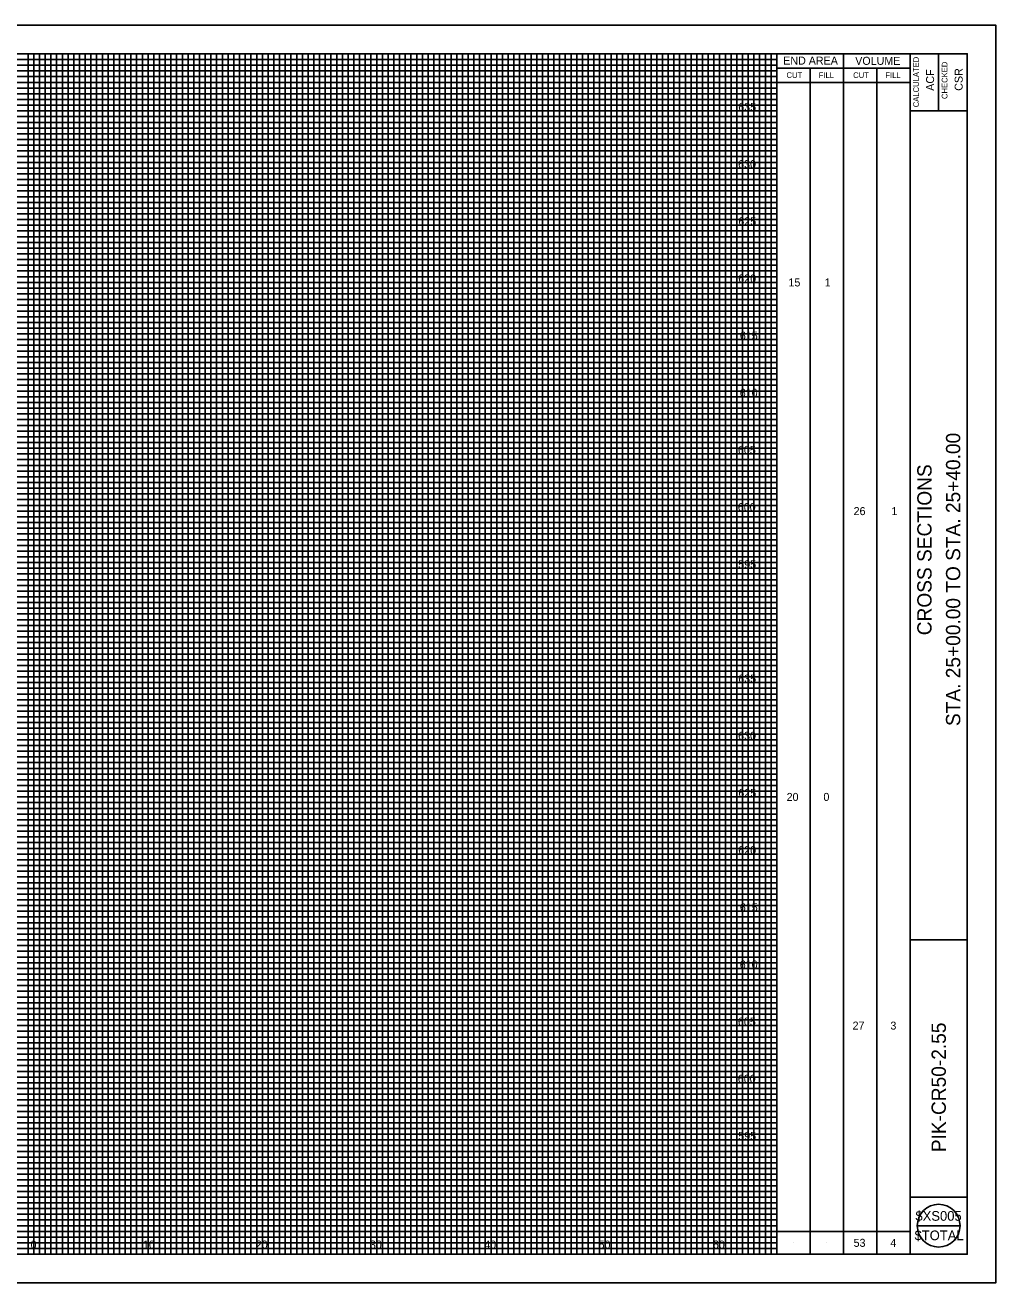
# Model space of a CAD drawing. Extents: x 1858928 to 1859278, y 421672 to 422012.
# Drawn here: x 1859192.6 to 1859277.5, y 421786.6 to 421896.6 of the extents above; entities that cross this region are included whole.
import ezdxf

# ---------------------------------------------------------------- set-up
doc = ezdxf.new("R2010")
doc.units = 0
for name, color, linetype in [('SH_Border', 7, 'Continuous'), ('SH_Cut_Line', 7, 'Continuous'), ('SH_Data', 7, 'Continuous'), ('SH_Major_Grid_Line', 7, 'Continuous'), ('SH_Minor_Grid_Line', 7, 'Continuous'), ('SH_Text', 7, 'Continuous')]:
    doc.layers.add(name, color=color, linetype=linetype)

msp = doc.modelspace()

# ---------------------------------------------------------------- linework, layer by layer
at = {"layer": 'SH_Border'}
for p, q in [((1859270.03, 421789.11), (1859270.03, 421894.11)), ((1859272.53, 421894.11), (1859272.53, 421889.11)), ((1859270.03, 421889.11), (1859275.03, 421889.11)), ((1859270.03, 421816.61), (1859275.03, 421816.61)), ((1859270.03, 421794.11), (1859275.03, 421794.11))]:
    msp.add_line(p, q, dxfattribs=at)
msp.add_lwpolyline([(1859117.53, 421894.11), (1859275.03, 421894.11), (1859275.03, 421789.11), (1859117.53, 421789.11)], close=True, dxfattribs=at)
at = {"layer": 'SH_Cut_Line'}
msp.add_lwpolyline([(1859107.53, 421786.61), (1859277.53, 421786.61), (1859277.53, 421896.61), (1859107.53, 421896.61)], close=True, dxfattribs=at)
at = {"layer": 'SH_Data'}
for p, q in [((1859258.37, 421789.11), (1859258.37, 421894.11)), ((1859264.2, 421789.11), (1859264.2, 421894.11)), ((1859258.37, 421892.86), (1859270.03, 421892.86)), ((1859261.28, 421789.11), (1859261.28, 421892.86)), ((1859267.12, 421789.11), (1859267.12, 421892.86)), ((1859258.37, 421891.61), (1859270.03, 421891.61)), ((1859258.37, 421791.11), (1859270.03, 421791.11)), ((1859270.66, 421791.61), (1859274.41, 421791.61)), ((1859259.83, 421790.11), (1859259.83, 421790.11)), ((1859262.74, 421790.11), (1859262.74, 421790.11)), ((1859265.66, 421790.11), (1859265.66, 421790.11)), ((1859268.58, 421790.11), (1859268.58, 421790.11))]:
    msp.add_line(p, q, dxfattribs=at)
msp.add_circle((1859272.53, 421791.61), 1.87, dxfattribs=at)
at = {"layer": 'SH_Major_Grid_Line'}
for p, q in [((1859193.37, 421789.11), (1859193.37, 421894.11)), ((1859198.37, 421789.11), (1859198.37, 421894.11)), ((1859203.37, 421789.11), (1859203.37, 421894.11)), ((1859208.37, 421789.11), (1859208.37, 421894.11)), ((1859213.37, 421789.11), (1859213.37, 421894.11)), ((1859218.37, 421789.11), (1859218.37, 421894.11)), ((1859223.37, 421789.11), (1859223.37, 421894.11)), ((1859228.37, 421789.11), (1859228.37, 421894.11)), ((1859233.37, 421789.11), (1859233.37, 421894.11)), ((1859238.37, 421789.11), (1859238.37, 421894.11)), ((1859243.37, 421789.11), (1859243.37, 421894.11)), ((1859248.37, 421789.11), (1859248.37, 421894.11)), ((1859253.37, 421789.11), (1859253.37, 421894.11)), ((1859123.37, 421889.11), (1859258.37, 421889.11)), ((1859123.37, 421884.11), (1859258.37, 421884.11)), ((1859123.37, 421879.11), (1859258.37, 421879.11)), ((1859123.37, 421874.11), (1859258.37, 421874.11)), ((1859123.37, 421869.11), (1859258.37, 421869.11)), ((1859123.37, 421864.11), (1859258.37, 421864.11)), ((1859123.37, 421859.11), (1859258.37, 421859.11)), ((1859123.37, 421854.11), (1859258.37, 421854.11)), ((1859123.37, 421849.11), (1859258.37, 421849.11)), ((1859123.37, 421844.11), (1859258.37, 421844.11)), ((1859123.37, 421839.11), (1859258.37, 421839.11)), ((1859123.37, 421834.11), (1859258.37, 421834.11)), ((1859123.37, 421829.11), (1859258.37, 421829.11)), ((1859123.37, 421824.11), (1859258.37, 421824.11)), ((1859123.37, 421819.11), (1859258.37, 421819.11)), ((1859123.37, 421814.11), (1859258.37, 421814.11)), ((1859123.37, 421809.11), (1859258.37, 421809.11)), ((1859123.37, 421804.11), (1859258.37, 421804.11)), ((1859123.37, 421799.11), (1859258.37, 421799.11)), ((1859123.37, 421794.11), (1859258.37, 421794.11))]:
    msp.add_line(p, q, dxfattribs=at)
at = {"layer": 'SH_Minor_Grid_Line'}
for p, q in [((1859192.87, 421789.11), (1859192.87, 421894.11)), ((1859193.87, 421789.11), (1859193.87, 421894.11)), ((1859194.37, 421789.11), (1859194.37, 421894.11)), ((1859194.87, 421789.11), (1859194.87, 421894.11)), ((1859195.37, 421789.11), (1859195.37, 421894.11)), ((1859195.87, 421789.11), (1859195.87, 421894.11)), ((1859196.37, 421789.11), (1859196.37, 421894.11)), ((1859196.87, 421789.11), (1859196.87, 421894.11)), ((1859197.37, 421789.11), (1859197.37, 421894.11)), ((1859197.87, 421789.11), (1859197.87, 421894.11)), ((1859198.87, 421789.11), (1859198.87, 421894.11)), ((1859199.37, 421789.11), (1859199.37, 421894.11)), ((1859199.87, 421789.11), (1859199.87, 421894.11)), ((1859200.37, 421789.11), (1859200.37, 421894.11)), ((1859200.87, 421789.11), (1859200.87, 421894.11)), ((1859201.37, 421789.11), (1859201.37, 421894.11)), ((1859201.87, 421789.11), (1859201.87, 421894.11)), ((1859202.37, 421789.11), (1859202.37, 421894.11)), ((1859202.87, 421789.11), (1859202.87, 421894.11)), ((1859203.87, 421789.11), (1859203.87, 421894.11)), ((1859204.37, 421789.11), (1859204.37, 421894.11)), ((1859204.87, 421789.11), (1859204.87, 421894.11)), ((1859205.37, 421789.11), (1859205.37, 421894.11)), ((1859205.87, 421789.11), (1859205.87, 421894.11)), ((1859206.37, 421789.11), (1859206.37, 421894.11)), ((1859206.87, 421789.11), (1859206.87, 421894.11)), ((1859207.37, 421789.11), (1859207.37, 421894.11)), ((1859207.87, 421789.11), (1859207.87, 421894.11)), ((1859208.87, 421789.11), (1859208.87, 421894.11)), ((1859209.37, 421789.11), (1859209.37, 421894.11)), ((1859209.87, 421789.11), (1859209.87, 421894.11)), ((1859210.37, 421789.11), (1859210.37, 421894.11)), ((1859210.87, 421789.11), (1859210.87, 421894.11)), ((1859211.37, 421789.11), (1859211.37, 421894.11)), ((1859211.87, 421789.11), (1859211.87, 421894.11)), ((1859212.37, 421789.11), (1859212.37, 421894.11)), ((1859212.87, 421789.11), (1859212.87, 421894.11)), ((1859213.87, 421789.11), (1859213.87, 421894.11)), ((1859214.37, 421789.11), (1859214.37, 421894.11)), ((1859214.87, 421789.11), (1859214.87, 421894.11)), ((1859215.37, 421789.11), (1859215.37, 421894.11)), ((1859215.87, 421789.11), (1859215.87, 421894.11)), ((1859216.37, 421789.11), (1859216.37, 421894.11)), ((1859216.87, 421789.11), (1859216.87, 421894.11)), ((1859217.37, 421789.11), (1859217.37, 421894.11)), ((1859217.87, 421789.11), (1859217.87, 421894.11)), ((1859218.87, 421789.11), (1859218.87, 421894.11)), ((1859219.37, 421789.11), (1859219.37, 421894.11)), ((1859219.87, 421789.11), (1859219.87, 421894.11)), ((1859220.37, 421789.11), (1859220.37, 421894.11)), ((1859220.87, 421789.11), (1859220.87, 421894.11)), ((1859221.37, 421789.11), (1859221.37, 421894.11)), ((1859221.87, 421789.11), (1859221.87, 421894.11)), ((1859222.37, 421789.11), (1859222.37, 421894.11)), ((1859222.87, 421789.11), (1859222.87, 421894.11)), ((1859223.87, 421789.11), (1859223.87, 421894.11)), ((1859224.37, 421789.11), (1859224.37, 421894.11)), ((1859224.87, 421789.11), (1859224.87, 421894.11)), ((1859225.37, 421789.11), (1859225.37, 421894.11)), ((1859225.87, 421789.11), (1859225.87, 421894.11)), ((1859226.37, 421789.11), (1859226.37, 421894.11)), ((1859226.87, 421789.11), (1859226.87, 421894.11)), ((1859227.37, 421789.11), (1859227.37, 421894.11)), ((1859227.87, 421789.11), (1859227.87, 421894.11)), ((1859228.87, 421789.11), (1859228.87, 421894.11)), ((1859229.37, 421789.11), (1859229.37, 421894.11)), ((1859229.87, 421789.11), (1859229.87, 421894.11)), ((1859230.37, 421789.11), (1859230.37, 421894.11)), ((1859230.87, 421789.11), (1859230.87, 421894.11)), ((1859231.37, 421789.11), (1859231.37, 421894.11)), ((1859231.87, 421789.11), (1859231.87, 421894.11)), ((1859232.37, 421789.11), (1859232.37, 421894.11)), ((1859232.87, 421789.11), (1859232.87, 421894.11)), ((1859233.87, 421789.11), (1859233.87, 421894.11)), ((1859234.37, 421789.11), (1859234.37, 421894.11)), ((1859234.87, 421789.11), (1859234.87, 421894.11)), ((1859235.37, 421789.11), (1859235.37, 421894.11)), ((1859235.87, 421789.11), (1859235.87, 421894.11)), ((1859236.37, 421789.11), (1859236.37, 421894.11)), ((1859236.87, 421789.11), (1859236.87, 421894.11)), ((1859237.37, 421789.11), (1859237.37, 421894.11)), ((1859237.87, 421789.11), (1859237.87, 421894.11)), ((1859238.87, 421789.11), (1859238.87, 421894.11)), ((1859239.37, 421789.11), (1859239.37, 421894.11)), ((1859239.87, 421789.11), (1859239.87, 421894.11)), ((1859240.37, 421789.11), (1859240.37, 421894.11)), ((1859240.87, 421789.11), (1859240.87, 421894.11)), ((1859241.37, 421789.11), (1859241.37, 421894.11)), ((1859241.87, 421789.11), (1859241.87, 421894.11)), ((1859242.37, 421789.11), (1859242.37, 421894.11)), ((1859242.87, 421789.11), (1859242.87, 421894.11)), ((1859243.87, 421789.11), (1859243.87, 421894.11)), ((1859244.37, 421789.11), (1859244.37, 421894.11)), ((1859244.87, 421789.11), (1859244.87, 421894.11)), ((1859245.37, 421789.11), (1859245.37, 421894.11)), ((1859245.87, 421789.11), (1859245.87, 421894.11)), ((1859246.37, 421789.11), (1859246.37, 421894.11)), ((1859246.87, 421789.11), (1859246.87, 421894.11)), ((1859247.37, 421789.11), (1859247.37, 421894.11)), ((1859247.87, 421789.11), (1859247.87, 421894.11)), ((1859248.87, 421789.11), (1859248.87, 421894.11)), ((1859249.37, 421789.11), (1859249.37, 421894.11)), ((1859249.87, 421789.11), (1859249.87, 421894.11)), ((1859250.37, 421789.11), (1859250.37, 421894.11)), ((1859250.87, 421789.11), (1859250.87, 421894.11)), ((1859251.37, 421789.11), (1859251.37, 421894.11)), ((1859251.87, 421789.11), (1859251.87, 421894.11)), ((1859252.37, 421789.11), (1859252.37, 421894.11)), ((1859252.87, 421789.11), (1859252.87, 421894.11)), ((1859253.87, 421789.11), (1859253.87, 421894.11)), ((1859254.37, 421789.11), (1859254.37, 421894.11)), ((1859254.87, 421789.11), (1859254.87, 421894.11)), ((1859255.37, 421789.11), (1859255.37, 421894.11)), ((1859255.87, 421789.11), (1859255.87, 421894.11)), ((1859256.37, 421789.11), (1859256.37, 421894.11)), ((1859256.87, 421789.11), (1859256.87, 421894.11)), ((1859257.37, 421789.11), (1859257.37, 421894.11)), ((1859257.87, 421789.11), (1859257.87, 421894.11)), ((1859123.37, 421893.61), (1859258.37, 421893.61)), ((1859123.37, 421893.11), (1859258.37, 421893.11)), ((1859123.37, 421892.61), (1859258.37, 421892.61)), ((1859123.37, 421892.11), (1859258.37, 421892.11)), ((1859123.37, 421891.61), (1859258.37, 421891.61)), ((1859123.37, 421891.11), (1859258.37, 421891.11)), ((1859123.37, 421890.61), (1859258.37, 421890.61)), ((1859123.37, 421890.11), (1859258.37, 421890.11)), ((1859123.37, 421889.61), (1859258.37, 421889.61)), ((1859123.37, 421888.61), (1859258.37, 421888.61)), ((1859123.37, 421888.11), (1859258.37, 421888.11)), ((1859123.37, 421887.61), (1859258.37, 421887.61)), ((1859123.37, 421887.11), (1859258.37, 421887.11)), ((1859123.37, 421886.61), (1859258.37, 421886.61)), ((1859123.37, 421886.11), (1859258.37, 421886.11)), ((1859123.37, 421885.61), (1859258.37, 421885.61)), ((1859123.37, 421885.11), (1859258.37, 421885.11)), ((1859123.37, 421884.61), (1859258.37, 421884.61)), ((1859123.37, 421883.61), (1859258.37, 421883.61)), ((1859123.37, 421883.11), (1859258.37, 421883.11)), ((1859123.37, 421882.61), (1859258.37, 421882.61)), ((1859123.37, 421882.11), (1859258.37, 421882.11)), ((1859123.37, 421881.61), (1859258.37, 421881.61)), ((1859123.37, 421881.11), (1859258.37, 421881.11)), ((1859123.37, 421880.61), (1859258.37, 421880.61)), ((1859123.37, 421880.11), (1859258.37, 421880.11)), ((1859123.37, 421879.61), (1859258.37, 421879.61)), ((1859123.37, 421878.61), (1859258.37, 421878.61)), ((1859123.37, 421878.11), (1859258.37, 421878.11)), ((1859123.37, 421877.61), (1859258.37, 421877.61)), ((1859123.37, 421877.11), (1859258.37, 421877.11)), ((1859123.37, 421876.61), (1859258.37, 421876.61)), ((1859123.37, 421876.11), (1859258.37, 421876.11)), ((1859123.37, 421875.61), (1859258.37, 421875.61)), ((1859123.37, 421875.11), (1859258.37, 421875.11)), ((1859123.37, 421874.61), (1859258.37, 421874.61)), ((1859123.37, 421873.61), (1859258.37, 421873.61)), ((1859123.37, 421873.11), (1859258.37, 421873.11)), ((1859123.37, 421872.61), (1859258.37, 421872.61)), ((1859123.37, 421872.11), (1859258.37, 421872.11)), ((1859123.37, 421871.61), (1859258.37, 421871.61)), ((1859123.37, 421871.11), (1859258.37, 421871.11)), ((1859123.37, 421870.61), (1859258.37, 421870.61)), ((1859123.37, 421870.11), (1859258.37, 421870.11)), ((1859123.37, 421869.61), (1859258.37, 421869.61)), ((1859123.37, 421868.61), (1859258.37, 421868.61)), ((1859123.37, 421868.11), (1859258.37, 421868.11)), ((1859123.37, 421867.61), (1859258.37, 421867.61)), ((1859123.37, 421867.11), (1859258.37, 421867.11)), ((1859123.37, 421866.61), (1859258.37, 421866.61)), ((1859123.37, 421866.11), (1859258.37, 421866.11)), ((1859123.37, 421865.61), (1859258.37, 421865.61)), ((1859123.37, 421865.11), (1859258.37, 421865.11)), ((1859123.37, 421864.61), (1859258.37, 421864.61)), ((1859123.37, 421863.61), (1859258.37, 421863.61)), ((1859123.37, 421863.11), (1859258.37, 421863.11)), ((1859123.37, 421862.61), (1859258.37, 421862.61)), ((1859123.37, 421862.11), (1859258.37, 421862.11)), ((1859123.37, 421861.61), (1859258.37, 421861.61)), ((1859123.37, 421861.11), (1859258.37, 421861.11)), ((1859123.37, 421860.61), (1859258.37, 421860.61)), ((1859123.37, 421860.11), (1859258.37, 421860.11)), ((1859123.37, 421859.61), (1859258.37, 421859.61)), ((1859123.37, 421858.61), (1859258.37, 421858.61)), ((1859123.37, 421858.11), (1859258.37, 421858.11)), ((1859123.37, 421857.61), (1859258.37, 421857.61)), ((1859123.37, 421857.11), (1859258.37, 421857.11)), ((1859123.37, 421856.61), (1859258.37, 421856.61)), ((1859123.37, 421856.11), (1859258.37, 421856.11)), ((1859123.37, 421855.61), (1859258.37, 421855.61)), ((1859123.37, 421855.11), (1859258.37, 421855.11)), ((1859123.37, 421854.61), (1859258.37, 421854.61)), ((1859123.37, 421853.61), (1859258.37, 421853.61)), ((1859123.37, 421853.11), (1859258.37, 421853.11)), ((1859123.37, 421852.61), (1859258.37, 421852.61)), ((1859123.37, 421852.11), (1859258.37, 421852.11)), ((1859123.37, 421851.61), (1859258.37, 421851.61)), ((1859123.37, 421851.11), (1859258.37, 421851.11)), ((1859123.37, 421850.61), (1859258.37, 421850.61)), ((1859123.37, 421850.11), (1859258.37, 421850.11)), ((1859123.37, 421849.61), (1859258.37, 421849.61)), ((1859123.37, 421848.61), (1859258.37, 421848.61)), ((1859123.37, 421848.11), (1859258.37, 421848.11)), ((1859123.37, 421847.61), (1859258.37, 421847.61)), ((1859123.37, 421847.11), (1859258.37, 421847.11)), ((1859123.37, 421846.61), (1859258.37, 421846.61)), ((1859123.37, 421846.11), (1859258.37, 421846.11)), ((1859123.37, 421845.61), (1859258.37, 421845.61)), ((1859123.37, 421845.11), (1859258.37, 421845.11)), ((1859123.37, 421844.61), (1859258.37, 421844.61)), ((1859123.37, 421843.61), (1859258.37, 421843.61)), ((1859123.37, 421843.11), (1859258.37, 421843.11)), ((1859123.37, 421842.61), (1859258.37, 421842.61)), ((1859123.37, 421842.11), (1859258.37, 421842.11)), ((1859123.37, 421841.61), (1859258.37, 421841.61)), ((1859123.37, 421841.11), (1859258.37, 421841.11)), ((1859123.37, 421840.61), (1859258.37, 421840.61)), ((1859123.37, 421840.11), (1859258.37, 421840.11)), ((1859123.37, 421839.61), (1859258.37, 421839.61)), ((1859123.37, 421838.61), (1859258.37, 421838.61)), ((1859123.37, 421838.11), (1859258.37, 421838.11)), ((1859123.37, 421837.61), (1859258.37, 421837.61)), ((1859123.37, 421837.11), (1859258.37, 421837.11)), ((1859123.37, 421836.61), (1859258.37, 421836.61)), ((1859123.37, 421836.11), (1859258.37, 421836.11)), ((1859123.37, 421835.61), (1859258.37, 421835.61)), ((1859123.37, 421835.11), (1859258.37, 421835.11)), ((1859123.37, 421834.61), (1859258.37, 421834.61)), ((1859123.37, 421833.61), (1859258.37, 421833.61)), ((1859123.37, 421833.11), (1859258.37, 421833.11)), ((1859123.37, 421832.61), (1859258.37, 421832.61)), ((1859123.37, 421832.11), (1859258.37, 421832.11)), ((1859123.37, 421831.61), (1859258.37, 421831.61)), ((1859123.37, 421831.11), (1859258.37, 421831.11)), ((1859123.37, 421830.61), (1859258.37, 421830.61)), ((1859123.37, 421830.11), (1859258.37, 421830.11)), ((1859123.37, 421829.61), (1859258.37, 421829.61)), ((1859123.37, 421828.61), (1859258.37, 421828.61)), ((1859123.37, 421828.11), (1859258.37, 421828.11)), ((1859123.37, 421827.61), (1859258.37, 421827.61)), ((1859123.37, 421827.11), (1859258.37, 421827.11)), ((1859123.37, 421826.61), (1859258.37, 421826.61)), ((1859123.37, 421826.11), (1859258.37, 421826.11)), ((1859123.37, 421825.61), (1859258.37, 421825.61)), ((1859123.37, 421825.11), (1859258.37, 421825.11)), ((1859123.37, 421824.61), (1859258.37, 421824.61)), ((1859123.37, 421823.61), (1859258.37, 421823.61)), ((1859123.37, 421823.11), (1859258.37, 421823.11)), ((1859123.37, 421822.61), (1859258.37, 421822.61)), ((1859123.37, 421822.11), (1859258.37, 421822.11)), ((1859123.37, 421821.61), (1859258.37, 421821.61)), ((1859123.37, 421821.11), (1859258.37, 421821.11)), ((1859123.37, 421820.61), (1859258.37, 421820.61)), ((1859123.37, 421820.11), (1859258.37, 421820.11)), ((1859123.37, 421819.61), (1859258.37, 421819.61)), ((1859123.37, 421818.61), (1859258.37, 421818.61)), ((1859123.37, 421818.11), (1859258.37, 421818.11)), ((1859123.37, 421817.61), (1859258.37, 421817.61)), ((1859123.37, 421817.11), (1859258.37, 421817.11)), ((1859123.37, 421816.61), (1859258.37, 421816.61)), ((1859123.37, 421816.11), (1859258.37, 421816.11)), ((1859123.37, 421815.61), (1859258.37, 421815.61)), ((1859123.37, 421815.11), (1859258.37, 421815.11)), ((1859123.37, 421814.61), (1859258.37, 421814.61)), ((1859123.37, 421813.61), (1859258.37, 421813.61)), ((1859123.37, 421813.11), (1859258.37, 421813.11)), ((1859123.37, 421812.61), (1859258.37, 421812.61)), ((1859123.37, 421812.11), (1859258.37, 421812.11)), ((1859123.37, 421811.61), (1859258.37, 421811.61)), ((1859123.37, 421811.11), (1859258.37, 421811.11)), ((1859123.37, 421810.61), (1859258.37, 421810.61)), ((1859123.37, 421810.11), (1859258.37, 421810.11)), ((1859123.37, 421809.61), (1859258.37, 421809.61)), ((1859123.37, 421808.61), (1859258.37, 421808.61)), ((1859123.37, 421808.11), (1859258.37, 421808.11)), ((1859123.37, 421807.61), (1859258.37, 421807.61)), ((1859123.37, 421807.11), (1859258.37, 421807.11)), ((1859123.37, 421806.61), (1859258.37, 421806.61)), ((1859123.37, 421806.11), (1859258.37, 421806.11)), ((1859123.37, 421805.61), (1859258.37, 421805.61)), ((1859123.37, 421805.11), (1859258.37, 421805.11)), ((1859123.37, 421804.61), (1859258.37, 421804.61)), ((1859123.37, 421803.61), (1859258.37, 421803.61)), ((1859123.37, 421803.11), (1859258.37, 421803.11)), ((1859123.37, 421802.61), (1859258.37, 421802.61)), ((1859123.37, 421802.11), (1859258.37, 421802.11)), ((1859123.37, 421801.61), (1859258.37, 421801.61)), ((1859123.37, 421801.11), (1859258.37, 421801.11)), ((1859123.37, 421800.61), (1859258.37, 421800.61)), ((1859123.37, 421800.11), (1859258.37, 421800.11)), ((1859123.37, 421799.61), (1859258.37, 421799.61)), ((1859123.37, 421798.61), (1859258.37, 421798.61)), ((1859123.37, 421798.11), (1859258.37, 421798.11)), ((1859123.37, 421797.61), (1859258.37, 421797.61)), ((1859123.37, 421797.11), (1859258.37, 421797.11)), ((1859123.37, 421796.61), (1859258.37, 421796.61)), ((1859123.37, 421796.11), (1859258.37, 421796.11)), ((1859123.37, 421795.61), (1859258.37, 421795.61)), ((1859123.37, 421795.11), (1859258.37, 421795.11)), ((1859123.37, 421794.61), (1859258.37, 421794.61)), ((1859123.37, 421793.61), (1859258.37, 421793.61)), ((1859123.37, 421793.11), (1859258.37, 421793.11)), ((1859123.37, 421792.61), (1859258.37, 421792.61)), ((1859123.37, 421792.11), (1859258.37, 421792.11)), ((1859123.37, 421791.61), (1859258.37, 421791.61)), ((1859123.37, 421791.11), (1859258.37, 421791.11)), ((1859123.37, 421790.61), (1859258.37, 421790.61)), ((1859123.37, 421790.11), (1859258.37, 421790.11)), ((1859123.37, 421789.61), (1859258.37, 421789.61))]:
    msp.add_line(p, q, dxfattribs=at)

# ---------------------------------------------------------------- texts
at = {"layer": 'SH_Data'}
for s, height, p in [('END AREA', 0.7, (1859258.93, 421893.16)), ('VOLUME', 0.7, (1859265.23, 421893.14)), ('CUT', 0.5, (1859259.22, 421891.99)), ('FILL', 0.5, (1859262.04, 421891.99)), ('CUT', 0.5, (1859265.05, 421891.99)), ('FILL', 0.5, (1859267.87, 421891.99)), ('$XS005', 0.85, (1859270.5, 421792.04)), ('$TOTAL', 0.85, (1859270.42, 421790.34))]:
    msp.add_text(s, height=height, dxfattribs=at).set_placement(p)
for s, height, p in [('CALCULATED', 0.5, (1859270.8, 421889.43)), ('CHECKED', 0.5, (1859273.3, 421890.15)), ('ACF', 0.7, (1859272.13, 421890.87)), ('CSR', 0.7, (1859274.63, 421890.87)), ('STA. 25+00.00 TO STA. 25+40.00', 1.25, (1859274.42, 421835.31)), ('CROSS SECTIONS', 1.25, (1859271.91, 421843.25)), ('PIK-CR50-2.55', 1.25, (1859273.16, 421798.04))]:
    msp.add_text(s, height=height, rotation=90, dxfattribs=at).set_placement(p)
at = {"layer": 'SH_Text'}
for s, p in [('635', (1859255, 421889.11)), ('630', (1859254.99, 421884.11)), ('625', (1859255.01, 421879.11)), ('620', (1859255, 421874.11)), ('15', (1859259.39, 421873.76)), ('1', (1859262.56, 421873.76)), ('615', (1859255.14, 421869.11)), ('610', (1859255.13, 421864.11)), ('605', (1859254.97, 421859.11)), ('600', (1859254.96, 421854.11)), ('26', (1859265.09, 421853.76)), ('1', (1859268.4, 421853.76)), ('595', (1859255, 421849.11)), ('635', (1859255, 421839.11)), ('630', (1859254.99, 421834.11)), ('625', (1859255.01, 421829.11)), ('20', (1859259.23, 421828.76)), ('0', (1859262.45, 421828.76)), ('620', (1859255, 421824.11)), ('615', (1859255.14, 421819.11)), ('610', (1859255.13, 421814.11)), ('605', (1859254.97, 421809.11)), ('27', (1859265, 421808.76)), ('3', (1859268.31, 421808.76)), ('600', (1859254.96, 421804.11)), ('595', (1859255, 421799.11)), ('0', (1859193.09, 421789.61)), ('0', (1859193.09, 421789.61)), ('10', (1859202.92, 421789.61)), ('20', (1859212.79, 421789.61)), ('30', (1859222.78, 421789.61)), ('40', (1859232.78, 421789.61)), ('50', (1859242.78, 421789.61)), ('60', (1859252.78, 421789.61)), ('53', (1859265.09, 421789.76)), ('4', (1859268.3, 421789.76))]:
    msp.add_text(s, height=0.7, dxfattribs=at).set_placement(p)

doc.saveas('drawing.dxf')
